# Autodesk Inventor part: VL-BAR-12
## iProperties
Created: 2005-08
Part Number: VL-BAR-12
Document SubType Name: Sheet Metal
Density: 1 g/cm^3
Mass: 2.02888 g
Surface Area: 39.3158 cm^2
Volume: 2.02888 cm^3
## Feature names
1. Rectangular Pattern1
2. Plate1
